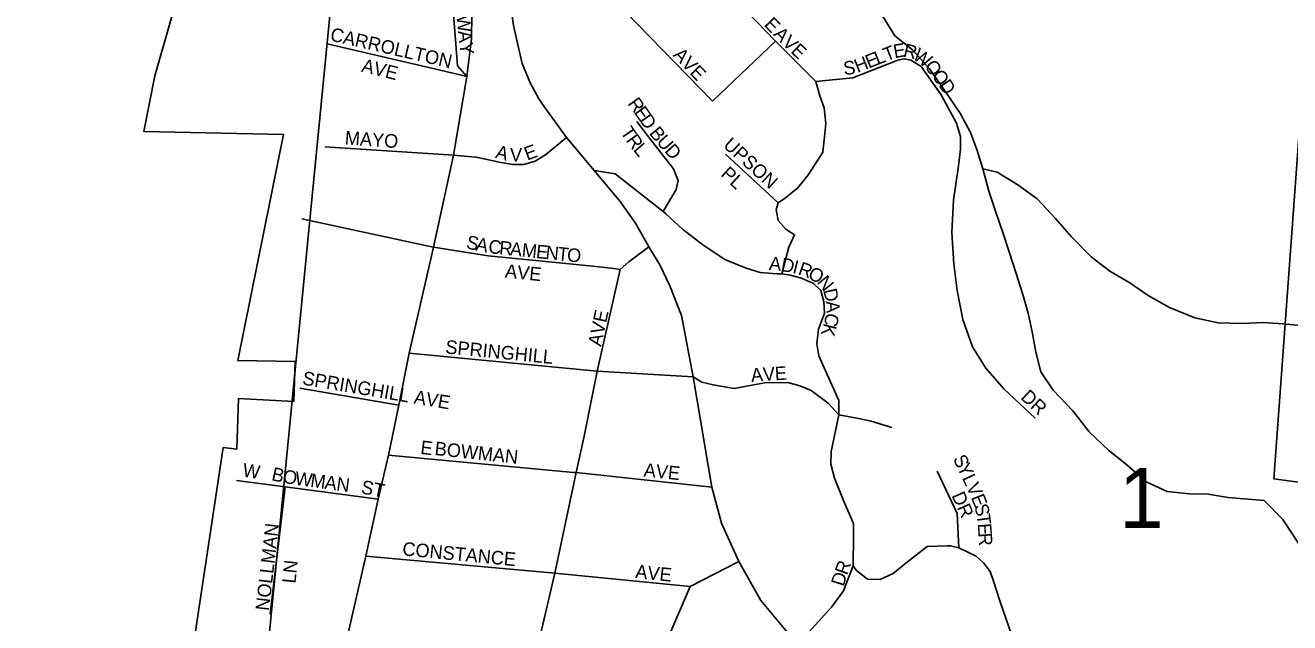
# Model space of a CAD drawing. Extents: x -209 to 4852, y 0 to 905.
# Drawn here: x 536.44 to 554.08, y 322.06 to 330.39 of the extents above; entities that cross this region are included whole.
import ezdxf

# ---------------------------------------------------------------- set-up
doc = ezdxf.new("R2010")
doc.units = 0
for name, color, linetype in [('GM_X_Airport_Location_Class_2', 7, 'Continuous'), ('GM_X_Airport_Location_Class_3', 7, 'Continuous'), ('GM_X_County_Road', 7, 'Continuous'), ('GM_X_Minor_River', 7, 'Continuous'), ('GM_X_Township_Road_Text', 7, 'Continuous'), ('GM_X_US_Location', 7, 'Continuous')]:
    doc.layers.add(name, color=color, linetype=linetype)

msp = doc.modelspace()

# ---------------------------------------------------------------- linework, layer by layer
at = {"layer": 'GM_X_Airport_Location_Class_2'}
for points in [[(540.864, 321.548), (541.196, 322.984), (541.368, 323.781), (541.512, 324.395), (541.657, 325.091), (541.8, 325.815), (542.139, 327.293), (542.418, 328.579), (542.606, 329.677), (542.668, 330.202), (542.673, 330.544), (542.627, 330.87), (542.425, 331.613), (542.119, 332.639), (542.099, 333.13), (542.103, 333.525), (542.156, 333.879), (542.273, 334.441), (542.393, 334.87), (542.647, 335.808), (542.738, 336.281), (542.749, 336.351)], [(542.606, 329.677), (542.475, 329.826), (542.408, 330.667), (542.346, 331.138), (542.151, 331.66), (541.815, 332.568)], [(547.46, 329.619), (546.909, 330.167), (545.956, 331.16), (545.34, 331.8), (545.142, 331.99), (545.054, 332.139), (544.979, 332.378)], [(543.668, 331.951), (543.723, 331.77), (543.79, 331.632), (544.057, 331.342), (544.814, 330.582), (546.032, 329.334)], [(543.694, 329.244), (543.608, 329.365), (543.486, 329.587), (543.377, 329.856), (543.322, 330.1), (543.256, 330.387), (543.058, 331.759)], [(540.654, 330.132), (542.172, 329.778)], [(546.032, 329.334), (546.909, 330.167)], [(550.531, 324.908), (550.094, 325.318), (549.842, 325.605), (549.658, 325.906), (549.522, 326.288), (549.444, 326.689), (549.397, 327.063), (549.371, 327.501), (549.391, 327.949), (549.462, 328.429), (549.492, 328.661), (549.489, 328.839), (549.436, 329.026), (549.221, 329.421), (548.94, 329.815), (548.797, 329.902), (548.705, 329.924), (548.615, 329.906), (547.987, 329.657), (547.471, 329.608)], [(542.172, 329.778), (542.389, 329.728)], [(542.389, 329.728), (542.606, 329.677)], [(546.997, 326.921), (547.096, 327.294), (547.176, 327.469), (547.054, 327.546), (546.947, 327.665), (546.918, 327.822), (546.949, 327.912), (547.051, 327.981), (547.221, 328.125), (547.37, 328.31), (547.568, 328.619), (547.592, 328.835), (547.612, 329.021), (547.588, 329.239), (547.526, 329.404), (547.471, 329.608), (547.46, 329.619)], [(544.31, 328.447), (543.992, 328.825), (543.694, 329.244)], [(545.342, 327.794), (545.522, 328.098), (545.552, 328.227), (545.488, 328.39), (545.151, 328.816), (544.973, 329.049)], [(542.759, 328.544), (543.078, 328.477), (543.244, 328.449), (543.398, 328.447), (543.558, 328.496), (543.7, 328.581), (543.992, 328.825)], [(540.624, 328.696), (542.418, 328.579), (542.725, 328.552), (542.759, 328.544)], [(545.138, 327.309), (544.956, 327.628), (544.745, 327.933), (544.378, 328.366), (544.31, 328.447)], [(546.949, 327.912), (546.211, 328.591)], [(545.381, 327.758), (545.342, 327.794), (544.671, 328.319), (544.378, 328.366)], [(546.931, 326.923), (546.868, 326.926), (546.697, 326.943), (546.499, 327.002), (546.203, 327.121), (545.896, 327.329), (545.614, 327.547), (545.381, 327.758)], [(540.304, 327.691), (542.068, 327.309)], [(542.068, 327.309), (542.139, 327.293), (542.902, 327.175), (544.361, 327.031), (544.654, 326.995)], [(544.654, 326.995), (544.745, 326.984), (544.862, 327.09), (545.143, 327.301)], [(547.224, 321.74), (547.215, 321.75), (546.705, 322.366), (546.396, 322.91), (546.156, 323.444), (546.023, 323.946), (545.763, 325.486), (545.599, 326.343), (545.436, 326.757), (545.297, 327.047), (545.143, 327.301), (545.138, 327.309)], [(543.165, 319.807), (543.497, 321.315), (543.832, 322.747), (544.129, 324.149), (544.241, 324.659), (544.421, 325.563), (544.745, 326.984)], [(547.97, 323.505), (547.868, 323.739), (547.733, 324.071), (547.68, 324.267), (547.684, 324.444), (547.794, 324.956), (547.794, 325.154), (547.719, 325.322), (547.606, 325.57), (547.516, 325.778), (547.487, 325.946), (547.511, 326.149), (547.591, 326.376), (547.584, 326.534), (547.541, 326.688), (547.442, 326.787), (547.274, 326.861), (547.116, 326.906), (546.997, 326.921), (546.931, 326.923)], [(541.8, 325.815), (544.421, 325.563), (545.759, 325.486)], [(545.759, 325.486), (545.763, 325.486), (545.882, 325.413), (546.038, 325.372), (546.332, 325.324), (546.756, 325.402), (547.084, 325.405), (547.251, 325.361), (547.408, 325.294), (547.646, 325.119), (547.794, 324.956), (548.043, 324.908), (548.245, 324.866), (548.532, 324.778)], [(540.275, 325.327), (541.657, 325.091)], [(541.512, 324.395), (544.091, 324.152)], [(539.389, 324.039), (540.07, 323.953), (541.368, 323.781)], [(544.091, 324.152), (544.129, 324.149), (546.023, 323.946)], [(549.467, 323.101), (549.444, 323.58), (549.166, 324.169)], [(539.861, 322.176), (540.07, 323.953)], [(549.309, 323.128), (549.027, 323.117), (548.728, 322.888), (548.552, 322.742), (548.372, 322.659), (548.195, 322.661), (548.038, 322.786), (547.993, 322.849), (547.999, 323.261), (547.999, 323.437), (547.97, 323.505)], [(541.196, 322.984), (543.832, 322.747), (545.719, 322.559)], [(550.382, 321.367), (550.04, 322.362), (549.952, 322.634), (549.905, 322.771), (549.811, 322.892), (549.708, 322.982), (549.467, 323.101), (549.35, 323.13), (549.309, 323.128)], [(545.064, 320.98), (545.098, 321.082), (545.254, 321.538), (545.436, 321.9), (545.719, 322.559), (546.396, 322.91)], [(547.19, 321.725), (547.215, 321.75), (547.415, 321.972), (547.69, 322.274), (547.857, 322.501), (547.921, 322.659), (547.993, 322.849)]]:
    msp.add_lwpolyline(points, dxfattribs=at)
at = {"layer": 'GM_X_County_Road'}
for points in [[(548.4, 330.523), (548.576, 330.245), (548.822, 330.049), (549.059, 329.784), (549.286, 329.459), (549.492, 329.157), (549.63, 328.896), (549.723, 328.642), (549.8, 328.389), (549.884, 328.076), (549.983, 327.784), (550.082, 327.5), (550.167, 327.232), (550.266, 326.926), (550.358, 326.634), (550.435, 326.374), (550.49, 326.114), (550.543, 325.831), (550.613, 325.556), (550.781, 325.301), (551.056, 325.013), (551.284, 324.718), (551.559, 324.46), (551.813, 324.256), (552.081, 324.021), (552.374, 323.885), (552.685, 323.854), (552.944, 323.848), (553.224, 323.803), (553.725, 323.76), (553.985, 323.495), (554.212, 323.155)], [(549.8, 328.389), (550.004, 328.339), (550.289, 328.164), (550.558, 327.968), (550.817, 327.695), (551.039, 327.438), (551.314, 327.158), (551.575, 326.961), (551.853, 326.795), (552.107, 326.621), (552.407, 326.454), (552.761, 326.308), (553.086, 326.239), (553.421, 326.231), (553.718, 326.246), (553.984, 326.224), (554.249, 326.203)]]:
    msp.add_lwpolyline(points, dxfattribs=at)
at = {"layer": 'GM_X_Minor_River'}
for points in [[(521.14, 336.64), (541.147, 335.189), (539.188, 315.131), (519.33, 316.881)], [(541.147, 335.189), (561.048, 333.339), (559.212, 313.354), (558.841, 313.406), (539.664, 315.099), (539.188, 315.131)]]:
    msp.add_lwpolyline(points, close=True, dxfattribs=at)
at = {"layer": 'GM_X_US_Location'}
for points in [[(538.489, 319.742), (539.206, 324.5), (539.394, 324.477), (539.42, 325.184), (540.192, 325.143), (540.21, 325.7), (539.407, 325.715), (540.047, 328.868), (538.1, 328.907), (538.251, 329.684), (539.07, 332.547), (530.617, 333.026)], [(539.07, 332.547), (538.251, 329.684), (538.1, 328.907), (540.047, 328.868), (539.407, 325.715), (540.21, 325.7), (540.192, 325.143), (539.42, 325.184), (539.394, 324.477), (539.206, 324.5), (538.489, 319.742)], [(539.07, 332.547), (538.251, 329.684), (538.1, 328.907), (540.047, 328.868), (539.407, 325.715), (540.21, 325.7), (540.192, 325.143), (539.42, 325.184), (539.394, 324.477), (539.206, 324.5), (538.489, 319.742)], [(555.506, 323.841), (553.861, 324.063), (554.261, 329.532)], [(554.261, 329.532), (553.861, 324.063), (555.506, 323.841)], [(555.506, 323.841), (553.861, 324.063), (554.261, 329.532)]]:
    msp.add_lwpolyline(points, dxfattribs=at)

# ---------------------------------------------------------------- texts
at = {"layer": 'GM_X_Airport_Location_Class_3'}
for s, height, rotation, p in [('W', 0.189, 275.8914, (542.458, 330.524)), ('E', 0.189, 313.572, (546.74, 330.393)), ('CARROLLTON', 0.1894, 347.0054, (540.686, 330.179)), ('A', 0.189, 276.0848, (542.48, 330.308)), ('A', 0.189, 314.7601, (546.869, 330.257)), ('V', 0.189, 316.5131, (546.991, 330.134)), ('Y', 0.189, 276.1071, (542.498, 330.142)), ('AVE', 0.1894, 313.5981, (545.47, 329.968)), ('E', 0.189, 316.5373, (547.112, 330.019)), ('E', 0.189, 21.7714, (548.209, 329.786)), ('L', 0.189, 21.7714, (548.333, 329.835)), ('T', 0.189, 21.7714, (548.457, 329.884)), ('E', 0.189, 9.9384, (548.571, 329.931)), ('R', 0.189, 346.8944, (548.682, 329.955)), ('W', 0.189, 325.4473, (548.811, 329.928)), ('AVE', 0.1894, 345.9638, (541.124, 329.746)), ('S', 0.189, 5.9661, (547.866, 329.696)), ('H', 0.189, 21.73, (548.054, 329.724)), ('O', 0.189, 308.3082, (548.979, 329.816)), ('O', 0.189, 306.3279, (549.081, 329.686)), ('D', 0.189, 304.7145, (549.179, 329.553)), ('R', 0.189, 305.6167, (544.84, 329.298)), ('E', 0.189, 305.6076, (544.928, 329.176)), ('D', 0.189, 305.5936, (545.005, 329.067)), ('T', 0.189, 303.781, (544.739, 328.901)), ('B', 0.189, 309.2677, (545.139, 328.881)), ('MAYO', 0.1894, 355.9166, (540.897, 328.729)), ('R', 0.189, 305.4932, (544.817, 328.786)), ('U', 0.189, 311.9099, (545.24, 328.758)), ('UPSON', 0.1894, 317.6413, (546.169, 328.703)), ('A', 0.189, 344.5321, (542.992, 328.544)), ('V', 0.189, 358.6642, (543.203, 328.492)), ('E', 0.189, 20.401, (543.446, 328.501)), ('L', 0.189, 310.9551, (544.916, 328.648)), ('D', 0.189, 312.0065, (545.352, 328.633)), ('PL', 0.1894, 317.4879, (546.134, 328.299)), ('S', 0.189, 348.2239, (542.585, 327.279)), ('A', 0.189, 348.8056, (542.718, 327.251)), ('C', 0.189, 352.7683, (542.896, 327.216)), ('R', 0.189, 354.0511, (543.049, 327.197)), ('A', 0.189, 354.0561, (543.198, 327.181)), ('M', 0.189, 354.0644, (543.364, 327.164)), ('E', 0.189, 354.0611, (543.563, 327.144)), ('N', 0.189, 354.0561, (543.696, 327.13)), ('T', 0.189, 354.07, (543.861, 327.112)), ('O', 0.189, 354.0654, (543.994, 327.099)), ('AVE', 0.1894, 354.0969, (543.131, 326.872)), ('A', 0.189, 354.6156, (546.814, 326.979)), ('D', 0.189, 349.8477, (546.976, 326.964)), ('I', 0.189, 346.091, (547.137, 326.936)), ('R', 0.189, 340.8509, (547.213, 326.917)), ('O', 0.189, 331.7244, (547.348, 326.871)), ('N', 0.189, 308.9295, (547.479, 326.804)), ('D', 0.189, 283.029, (547.574, 326.695)), ('A', 0.189, 274.2663, (547.611, 326.54)), ('AVE', 0.1894, 77.9042, (544.476, 325.901)), ('C', 0.189, 255.092, (547.625, 326.391)), ('K', 0.189, 255.7676, (547.585, 326.243)), ('SPRINGHILL', 0.1894, 354.3599, (542.298, 325.813)), ('A', 0.189, 4.9234, (546.574, 325.413)), ('V', 0.189, 3.6527, (546.739, 325.427)), ('E', 0.189, 3.198, (546.905, 325.437)), ('SPRINGHILL AVE', 0.18939, 350.3732, (540.301, 325.379)), ('DR', 0.1894, 317.1199, (550.319, 325.187)), ('E', 0.189, 352.8783, (541.949, 324.412)), ('BOWMAN', 0.1894, 353.8533, (542.148, 324.396)), ('S', 0.189, 295.0177, (549.381, 324.347)), ('W', 0.189, 351.2589, (539.467, 324.096)), ('B', 0.189, 347.1947, (539.869, 324.045)), ('AVE', 0.1894, 354.0969, (545.065, 324.096)), ('Y', 0.189, 295.0177, (549.438, 324.226)), ('O', 0.189, 350.2639, (540.027, 324.01)), ('W', 0.189, 352.3039, (540.198, 323.98)), ('M', 0.189, 352.3209, (540.413, 323.951)), ('A', 0.189, 352.3276, (540.611, 323.925)), ('N', 0.189, 352.3376, (540.776, 323.902)), ('ST', 0.1894, 348.6957, (541.118, 323.862)), ('L', 0.189, 295.0177, (549.508, 324.075)), ('V', 0.189, 295.0177, (549.564, 323.955)), ('DR', 0.1894, 293.9636, (549.362, 323.831)), ('E', 0.189, 291.5064, (549.634, 323.806)), ('S', 0.189, 284.4839, (549.681, 323.688)), ('T', 0.189, 277.4614, (549.713, 323.565)), ('NOLLMAN', 0.1894, 83.3839, (539.843, 322.215)), ('E', 0.189, 273.9501, (549.73, 323.436)), ('CONSTANCE', 0.1894, 354.4949, (541.698, 322.996)), ('R', 0.189, 273.9501, (549.739, 323.303)), ('LN', 0.1894, 83.9946, (540.213, 322.597)), ('AVE', 0.1894, 354.0969, (544.948, 322.679)), ('R', 0.189, 70.4589, (547.909, 322.71)), ('D', 0.189, 72.6434, (547.86, 322.552))]:
    msp.add_text(s, height=height, rotation=rotation, dxfattribs=at).set_placement(p)
at = {"layer": 'GM_X_Township_Road_Text'}
msp.add_text('1', height=0.837, rotation=0, dxfattribs=at).set_placement((551.703, 323.378))

doc.saveas('drawing.dxf')
